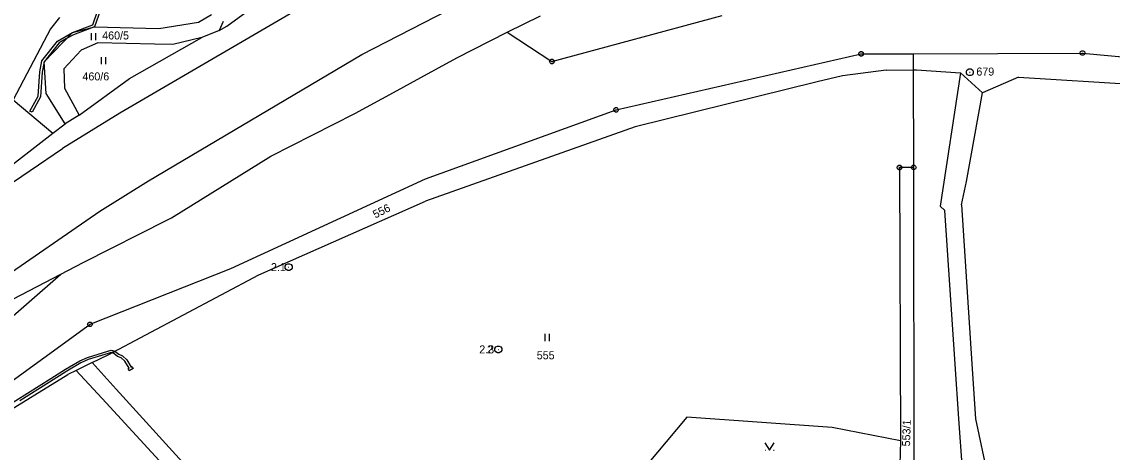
# Model space of a CAD drawing. Extents: x -759699 to -757730, y -1172308 to -1170857.
# Drawn here: x -759282.5 to -759051, y -1171766.9 to -1171675.5 of the extents above; entities that cross this region are included whole.
import ezdxf

# ---------------------------------------------------------------- set-up
doc = ezdxf.new("R2010")
doc.units = 0
for name, color, linetype in [('Vrstva 1', 7, 'Continuous'), ('Vrstva 13', 7, 'Continuous'), ('Vrstva 2', 7, 'Continuous'), ('Vrstva 3', 7, 'Continuous'), ('Vrstva 4', 7, 'Continuous'), ('Vrstva 8', 7, 'Continuous')]:
    doc.layers.add(name, color=color, linetype=linetype)

msp = doc.modelspace()

# ---------------------------------------------------------------- linework, layer by layer
at = {"layer": 'Vrstva 1'}
for p, q in [((-759238.96, -1171676.49), (-759231.42, -1171670.95)), ((-759244.98, -1171675.61), (-759242.21, -1171673.99)), ((-759179.45, -1171677.75), (-759172.37, -1171674.25)), ((-759169.95, -1171683.97), (-759133.84, -1171674.17)), ((-759274.51, -1171674.64), (-759276.45, -1171677.04)), ((-759253.39, -1171676.94), (-759244.98, -1171675.61)), ((-759239.78, -1171675.47), (-759240.6, -1171677.37)), ((-759240.6, -1171677.37), (-759238.96, -1171676.49)), ((-759276.45, -1171677.04), (-759284.37, -1171692.06)), ((-759277.76, -1171684.04), (-759271.78, -1171677.81)), ((-759271.78, -1171677.81), (-759267.07, -1171676.58)), ((-759267.07, -1171676.58), (-759253.39, -1171676.94)), ((-759259.64, -1171687.58), (-759244.31, -1171678.86)), ((-759244.31, -1171678.86), (-759250.43, -1171680.36)), ((-759240.6, -1171677.37), (-759244.31, -1171678.86)), ((-759190.16, -1171683.2), (-759179.45, -1171677.75)), ((-759179.45, -1171677.75), (-759169.95, -1171683.97)), ((-759266.39, -1171680.01), (-759269.88, -1171681.54)), ((-759254.36, -1171680.27), (-759266.39, -1171680.01)), ((-759250.43, -1171680.36), (-759254.36, -1171680.27)), ((-759269.88, -1171681.54), (-759273.62, -1171685.52)), ((-759197.8, -1171687.37), (-759190.16, -1171683.2)), ((-759156.33, -1171694.22), (-759104.3, -1171682.35)), ((-759104.3, -1171682.35), (-759093.25, -1171682.31)), ((-759093.25, -1171682.31), (-759057.29, -1171682.16)), ((-759093.25, -1171682.31), (-759093.23, -1171685.72)), ((-759057.29, -1171682.16), (-759030.21, -1171684.76)), ((-759277.34, -1171690.78), (-759277.76, -1171684.04)), ((-759273.62, -1171685.52), (-759273.42, -1171689.63)), ((-759099.02, -1171685.81), (-759108.23, -1171687)), ((-759099.02, -1171685.81), (-759093.23, -1171685.72)), ((-759093.23, -1171685.72), (-759092.54, -1171685.71)), ((-759093.23, -1171685.72), (-759093.15, -1171706.45)), ((-759092.54, -1171685.71), (-759083.22, -1171686.37)), ((-759270.32, -1171695.35), (-759259.64, -1171687.58)), ((-759203.56, -1171690.51), (-759197.8, -1171687.37)), ((-759108.23, -1171687), (-759113.66, -1171688.25)), ((-759083.22, -1171686.37), (-759087.5, -1171714.63)), ((-759078.55, -1171690.64), (-759083.22, -1171686.37)), ((-759070.89, -1171687.29), (-759078.55, -1171690.64)), ((-759070.89, -1171687.29), (-758925.35, -1171696.39)), ((-759273.42, -1171689.63), (-759270.32, -1171695.35)), ((-759113.66, -1171688.25), (-759152.25, -1171697.81)), ((-759284.37, -1171692.06), (-759275.95, -1171699.14)), ((-759273.28, -1171697.16), (-759277.34, -1171690.78)), ((-759211.78, -1171694.99), (-759203.56, -1171690.51)), ((-759081.92, -1171709.41), (-759078.55, -1171690.64)), ((-759229.62, -1171704.05), (-759211.78, -1171694.99)), ((-759196.77, -1171708.85), (-759156.33, -1171694.22)), ((-759275.95, -1171699.14), (-759273.28, -1171697.16)), ((-759270.32, -1171695.35), (-759273.28, -1171697.16)), ((-759297.8, -1171716.13), (-759275.95, -1171699.14)), ((-759152.25, -1171697.81), (-759196.79, -1171713.6)), ((-759250.71, -1171717.15), (-759229.62, -1171704.05)), ((-759093.15, -1171706.45), (-759096.15, -1171706.46)), ((-759096.15, -1171706.46), (-759095.93, -1171764.47)), ((-759093.15, -1171706.45), (-759093.12, -1171775.05)), ((-759238.11, -1171727.86), (-759196.77, -1171708.85)), ((-759083.01, -1171714.36), (-759081.92, -1171709.41)), ((-759232.22, -1171729.23), (-759196.79, -1171713.6)), ((-759087.5, -1171714.63), (-759086.54, -1171715.55)), ((-759084.33, -1171748.16), (-759086.54, -1171715.55)), ((-759083.01, -1171714.36), (-759080.79, -1171748.08)), ((-759269.46, -1171726.58), (-759251.56, -1171717.54)), ((-759251.56, -1171717.54), (-759250.71, -1171717.15)), ((-759274.24, -1171729.06), (-759269.46, -1171726.58)), ((-759291.6, -1171744.21), (-759274.24, -1171729.06)), ((-759289.91, -1171737.2), (-759274.24, -1171729.06)), ((-759268.03, -1171739.72), (-759238.11, -1171727.86)), ((-759264.15, -1171746.2), (-759232.22, -1171729.23)), ((-759302.49, -1171764.75), (-759268.03, -1171739.72)), ((-759267.58, -1171747.86), (-759270.95, -1171749.5)), ((-759267.58, -1171747.86), (-759264.15, -1171746.2)), ((-759262.47, -1171753.49), (-759267.58, -1171747.86)), ((-759083.59, -1171759.79), (-759084.33, -1171748.16)), ((-759080.79, -1171748.08), (-759079.99, -1171759.78)), ((-759296.84, -1171765.24), (-759272.77, -1171750.38)), ((-759270.95, -1171749.5), (-759272.77, -1171750.38)), ((-759270.95, -1171749.5), (-759264.61, -1171756.37)), ((-759262.47, -1171753.49), (-759202.22, -1171819.77)), ((-759264.61, -1171756.37), (-759204.35, -1171821.72)), ((-759141.29, -1171759.46), (-759189.7, -1171816.89)), ((-759110.43, -1171761.6), (-759141.29, -1171759.46)), ((-759082.76, -1171770.54), (-759083.59, -1171759.79)), ((-759079.99, -1171759.78), (-759077.24, -1171772.97)), ((-759095.93, -1171764.47), (-759110.43, -1171761.6)), ((-759095.93, -1171764.47), (-759096.25, -1171774.67))]:
    msp.add_line(p, q, dxfattribs=at)
at = {"layer": 'Vrstva 13'}
for p, q in [((-759267.46, -1171676.19), (-759265.31, -1171670.01)), ((-759264.85, -1171670.23), (-759267.07, -1171676.58)), ((-759271.78, -1171677.81), (-759267.46, -1171676.19)), ((-759274.93, -1171679.63), (-759271.78, -1171677.81)), ((-759271.57, -1171678.27), (-759273.03, -1171679.11)), ((-759267.07, -1171676.58), (-759271.57, -1171678.27)), ((-759278.23, -1171683.82), (-759274.93, -1171679.63)), ((-759274.6, -1171680.02), (-759277.76, -1171684.04)), ((-759273.03, -1171679.11), (-759274.6, -1171680.02)), ((-759278.7, -1171686.14), (-759278.23, -1171683.82)), ((-759277.76, -1171684.04), (-759278.2, -1171686.21)), ((-759279.04, -1171691.31), (-759278.7, -1171686.14)), ((-759278.2, -1171686.21), (-759278.54, -1171691.45)), ((-759280.79, -1171694.49), (-759279.04, -1171691.31)), ((-759278.54, -1171691.45), (-759280.35, -1171694.73)), ((-759280.35, -1171694.73), (-759280.79, -1171694.49)), ((-759268.59, -1171746.74), (-759264.28, -1171745.41)), ((-759264.15, -1171745.9), (-759268.42, -1171747.21)), ((-759264.28, -1171745.41), (-759263.57, -1171745.18)), ((-759263.57, -1171745.7), (-759264.15, -1171745.9)), ((-759263.57, -1171745.18), (-759262.75, -1171745.46)), ((-759263.35, -1171745.78), (-759263.57, -1171745.7)), ((-759263.35, -1171745.78), (-759262.75, -1171745.46)), ((-759262.75, -1171745.46), (-759263.35, -1171745.78)), ((-759262.99, -1171745.9), (-759263.35, -1171745.78)), ((-759262.17, -1171746.53), (-759262.99, -1171745.9)), ((-759262.75, -1171745.46), (-759261.93, -1171746.09)), ((-759273.22, -1171749.24), (-759270.22, -1171747.49)), ((-759269.98, -1171747.93), (-759272.95, -1171749.66)), ((-759270.22, -1171747.49), (-759268.59, -1171746.74)), ((-759268.42, -1171747.21), (-759269.98, -1171747.93)), ((-759261.42, -1171746.83), (-759262.17, -1171746.53)), ((-759261.93, -1171746.09), (-759261.16, -1171746.39)), ((-759260.61, -1171747.55), (-759261.42, -1171746.83)), ((-759261.16, -1171746.39), (-759260.21, -1171747.23)), ((-759259.74, -1171749.05), (-759260.61, -1171747.55)), ((-759260.21, -1171747.23), (-759259.31, -1171748.8)), ((-759272.95, -1171749.66), (-759276.66, -1171751.99)), ((-759276.37, -1171751.22), (-759273.22, -1171749.24)), ((-759259.96, -1171749.18), (-759259.74, -1171749.05)), ((-759259.71, -1171749.61), (-759259.96, -1171749.18)), ((-759258.85, -1171749.11), (-759259.71, -1171749.61)), ((-759259.31, -1171748.8), (-759259.1, -1171748.68)), ((-759259.1, -1171748.68), (-759258.85, -1171749.11)), ((-759276.66, -1171751.99), (-759282.93, -1171755.94)), ((-759281.29, -1171754.32), (-759276.37, -1171751.22)), ((-759286.25, -1171757.45), (-759281.29, -1171754.32))]:
    msp.add_line(p, q, dxfattribs=at)
at = {"layer": 'Vrstva 3'}
for p, q in [((-759267.81, -1171677.92), (-759267.81, -1171679.42)), ((-759266.81, -1171679.42), (-759266.81, -1171677.92)), ((-759265.69, -1171683.01), (-759265.69, -1171684.51)), ((-759264.69, -1171684.51), (-759264.69, -1171683.01)), ((-759171.44, -1171741.77), (-759171.44, -1171743.27)), ((-759170.44, -1171743.27), (-759170.44, -1171741.77)), ((-759124.69, -1171766.41), (-759124.59, -1171766.41)), ((-759122.89, -1171766.41), (-759122.79, -1171766.41))]:
    msp.add_line(p, q, dxfattribs=at)
msp.add_lwpolyline([(-759124.74, -1171764.91), (-759123.74, -1171766.41), (-759122.74, -1171764.91)], dxfattribs=at)
at = {"layer": 'Vrstva 4'}
for p, q in [((-759210.31, -1171682.44), (-759167.08, -1171660.23)), ((-759216.14, -1171668.33), (-759261.71, -1171694.89)), ((-759255.65, -1171709.31), (-759210.31, -1171682.44)), ((-759261.71, -1171694.89), (-759273.85, -1171702.42)), ((-759296.25, -1171717.55), (-759273.85, -1171702.42)), ((-759265.92, -1171715.74), (-759255.65, -1171709.31)), ((-759290.05, -1171732.29), (-759265.92, -1171715.74))]:
    msp.add_line(p, q, dxfattribs=at)
at = {"layer": 'Vrstva 8'}
for p, q in [((-759104.42, -1171682.35), (-759104.18, -1171682.35)), ((-759057.41, -1171682.16), (-759057.17, -1171682.16)), ((-759170.07, -1171683.97), (-759169.83, -1171683.97)), ((-759081.27, -1171686.23), (-759081.17, -1171686.23)), ((-759156.45, -1171694.22), (-759156.21, -1171694.22)), ((-759096.27, -1171706.46), (-759096.03, -1171706.46)), ((-759093.27, -1171706.45), (-759093.03, -1171706.45)), ((-759225.89, -1171727.59), (-759225.79, -1171727.59)), ((-759268.15, -1171739.72), (-759267.91, -1171739.72)), ((-759181.37, -1171745.05), (-759181.27, -1171745.05)), ((-759181.37, -1171745.05), (-759181.27, -1171745.05))]:
    msp.add_line(p, q, dxfattribs=at)
for points in [[(-759169.8, -1171683.49), (-759169.55, -1171683.67), (-759169.45, -1171683.96), (-759169.55, -1171684.25), (-759169.8, -1171684.43), (-759170.11, -1171684.43), (-759170.36, -1171684.25), (-759170.46, -1171683.96), (-759170.36, -1171683.67), (-759170.11, -1171683.49)], [(-759104.15, -1171681.87), (-759103.9, -1171682.05), (-759103.8, -1171682.34), (-759103.9, -1171682.63), (-759104.15, -1171682.81), (-759104.46, -1171682.81), (-759104.71, -1171682.63), (-759104.81, -1171682.34), (-759104.71, -1171682.05), (-759104.46, -1171681.87)], [(-759057.14, -1171681.68), (-759056.89, -1171681.86), (-759056.79, -1171682.15), (-759056.89, -1171682.44), (-759057.14, -1171682.62), (-759057.45, -1171682.62), (-759057.7, -1171682.44), (-759057.8, -1171682.15), (-759057.7, -1171681.86), (-759057.45, -1171681.68)], [(-759081.03, -1171685.51), (-759080.69, -1171685.7), (-759080.5, -1171686.04), (-759080.5, -1171686.43), (-759080.69, -1171686.77), (-759081.03, -1171686.96), (-759081.42, -1171686.96), (-759081.76, -1171686.77), (-759081.95, -1171686.43), (-759081.95, -1171686.04), (-759081.76, -1171685.7), (-759081.42, -1171685.51)], [(-759156.18, -1171693.74), (-759155.93, -1171693.92), (-759155.83, -1171694.21), (-759155.93, -1171694.5), (-759156.18, -1171694.68), (-759156.49, -1171694.68), (-759156.74, -1171694.5), (-759156.84, -1171694.21), (-759156.74, -1171693.92), (-759156.49, -1171693.74)], [(-759096, -1171705.98), (-759095.75, -1171706.16), (-759095.65, -1171706.45), (-759095.75, -1171706.74), (-759096, -1171706.92), (-759096.31, -1171706.92), (-759096.56, -1171706.74), (-759096.66, -1171706.45), (-759096.56, -1171706.16), (-759096.31, -1171705.98)], [(-759093, -1171705.97), (-759092.75, -1171706.15), (-759092.65, -1171706.44), (-759092.75, -1171706.73), (-759093, -1171706.91), (-759093.31, -1171706.91), (-759093.56, -1171706.73), (-759093.66, -1171706.44), (-759093.56, -1171706.15), (-759093.31, -1171705.97)], [(-759225.65, -1171726.87), (-759225.31, -1171727.06), (-759225.12, -1171727.4), (-759225.12, -1171727.79), (-759225.31, -1171728.13), (-759225.65, -1171728.32), (-759226.04, -1171728.32), (-759226.38, -1171728.13), (-759226.57, -1171727.79), (-759226.57, -1171727.4), (-759226.38, -1171727.06), (-759226.04, -1171726.87)], [(-759267.88, -1171739.24), (-759267.63, -1171739.42), (-759267.53, -1171739.71), (-759267.63, -1171740), (-759267.88, -1171740.18), (-759268.19, -1171740.18), (-759268.44, -1171740), (-759268.54, -1171739.71), (-759268.44, -1171739.42), (-759268.19, -1171739.24)], [(-759181.13, -1171744.33), (-759180.79, -1171744.52), (-759180.6, -1171744.86), (-759180.6, -1171745.25), (-759180.79, -1171745.59), (-759181.13, -1171745.78), (-759181.52, -1171745.78), (-759181.86, -1171745.59), (-759182.05, -1171745.25), (-759182.05, -1171744.86), (-759181.86, -1171744.52), (-759181.52, -1171744.33)], [(-759181.13, -1171744.33), (-759180.79, -1171744.52), (-759180.6, -1171744.86), (-759180.6, -1171745.25), (-759180.79, -1171745.59), (-759181.13, -1171745.78), (-759181.52, -1171745.78), (-759181.86, -1171745.59), (-759182.05, -1171745.25), (-759182.05, -1171744.86), (-759181.86, -1171744.52), (-759181.52, -1171744.33)]]:
    msp.add_lwpolyline(points, close=True, dxfattribs=at)

# ---------------------------------------------------------------- texts
at = {"layer": 'Vrstva 2'}
for s, p in [('460/5', (-759265.447, -1171679.28)), ('460/6', (-759269.64, -1171687.97)), ('555', (-759173.175, -1171747.15))]:
    msp.add_text(s, height=1.7, dxfattribs=at).set_placement(p)
for s, rotation, p in [('556', 26.69983, (-759207.46, -1171717.3)), ('553/1', 88.17821, (-759093.924, -1171765.654))]:
    msp.add_text(s, height=1.7, rotation=rotation, dxfattribs=at).set_placement(p)
at = {"layer": 'Vrstva 8'}
for s, p in [('679', (-759079.834, -1171686.95)), ('2.1', (-759229.621, -1171728.44)), ('2.3', (-759185.382, -1171745.9)), ('2', (-759183.733, -1171745.9))]:
    msp.add_text(s, height=1.7, dxfattribs=at).set_placement(p)

doc.saveas('drawing.dxf')
